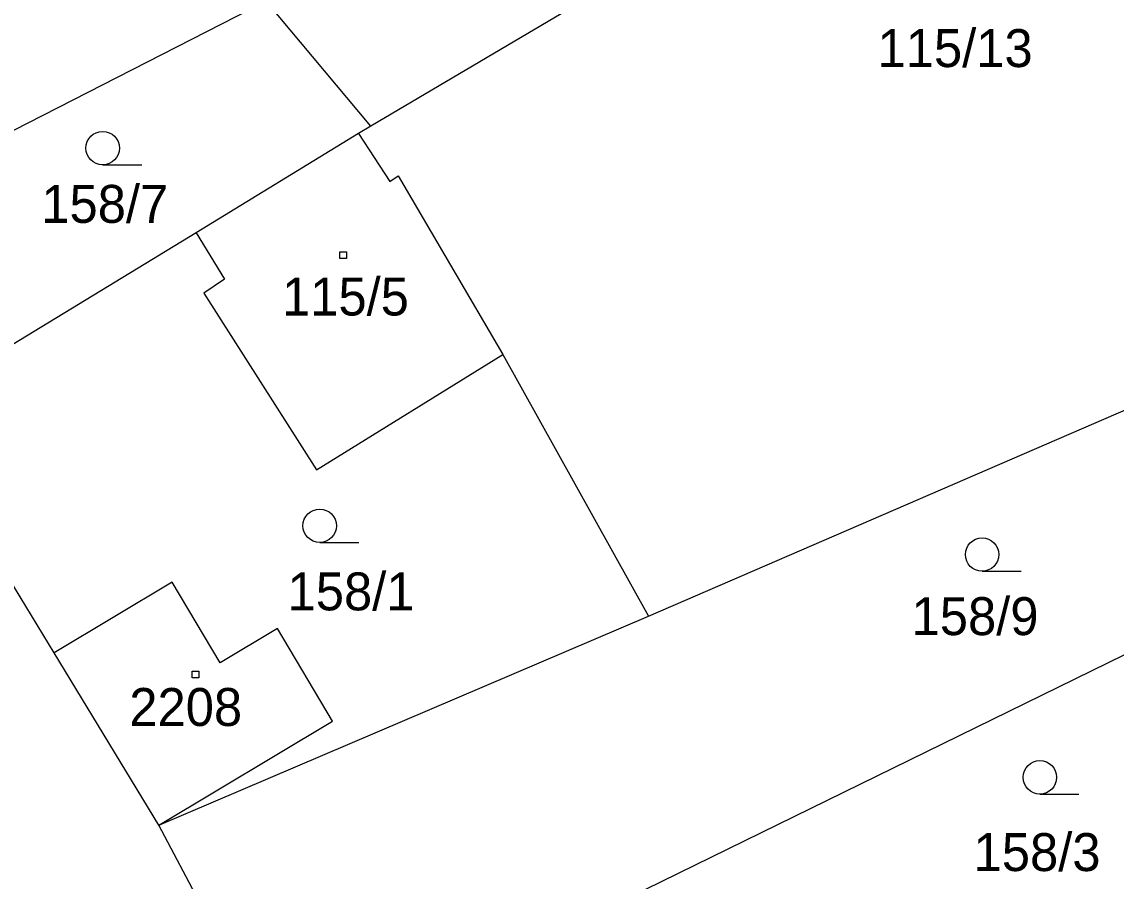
# Model space of a CAD drawing. Extents: x -711879 to -711361, y -1048782 to -1048177.
# Drawn here: x -711718.91 to -711669.86, y -1048658.13 to -1048619.64 of the extents above; entities that cross this region are included whole.
import ezdxf

# ---------------------------------------------------------------- set-up
doc = ezdxf.new("R2010")
doc.units = 0
for name, color, linetype in [('Vrstva 1', 7, 'Continuous'), ('Vrstva 14', 7, 'Continuous'), ('Vrstva 15', 7, 'Continuous'), ('Vrstva 16', 7, 'Continuous'), ('Vrstva 2', 7, 'Continuous'), ('Vrstva 23', 7, 'Continuous'), ('Vrstva 25', 7, 'Continuous'), ('Vrstva 46', 7, 'Continuous')]:
    doc.layers.add(name, color=color, linetype=linetype)

msp = doc.modelspace()

# ---------------------------------------------------------------- linework, layer by layer
at = {"layer": 'Vrstva 1'}
for p, q in [((-711692.51, -1048617.95), (-711703.27, -1048624.31)), ((-711719.96, -1048624.83), (-711707.96, -1048618.7)), ((-711703.27, -1048624.31), (-711707.96, -1048618.7)), ((-711703.27, -1048624.31), (-711703.82, -1048624.64)), ((-711703.82, -1048624.64), (-711711.1, -1048629.08)), ((-711711.1, -1048629.08), (-711724.1, -1048636.99)), ((-711711.1, -1048629.08), (-711709.83, -1048631.16)), ((-711709.83, -1048631.16), (-711710.76, -1048631.79)), ((-711710.76, -1048631.79), (-711705.71, -1048639.71)), ((-711690.83, -1048646.26), (-711663.05, -1048634.25)), ((-711705.71, -1048639.71), (-711697.35, -1048634.53)), ((-711697.35, -1048634.53), (-711690.83, -1048646.26)), ((-711717.47, -1048647.9), (-711724.1, -1048636.99)), ((-711647.12, -1048637.04), (-711707.08, -1048666.39)), ((-711712.17, -1048644.73), (-711717.47, -1048647.9)), ((-711710.02, -1048648.35), (-711712.17, -1048644.73)), ((-711712.77, -1048655.63), (-711690.83, -1048646.26)), ((-711707.45, -1048646.82), (-711710.02, -1048648.35)), ((-711704.99, -1048650.97), (-711707.45, -1048646.82)), ((-711712.77, -1048655.63), (-711717.47, -1048647.9)), ((-711712.77, -1048655.63), (-711704.99, -1048650.97)), ((-711707.08, -1048666.39), (-711712.77, -1048655.63))]:
    msp.add_line(p, q, dxfattribs=at)
at = {"layer": 'Vrstva 2'}
for p, q in [((-711703.82, -1048624.64), (-711702.42, -1048626.78)), ((-711702.42, -1048626.78), (-711702.04, -1048626.53)), ((-711702.04, -1048626.53), (-711697.35, -1048634.53))]:
    msp.add_line(p, q, dxfattribs=at)
at = {"layer": 'Vrstva 23'}
for p, q in [((-711715.29, -1048626.04), (-711713.54, -1048626.04)), ((-711705.56, -1048642.96), (-711703.81, -1048642.96)), ((-711675.87, -1048644.25), (-711674.12, -1048644.25)), ((-711673.28, -1048654.23), (-711671.53, -1048654.23))]:
    msp.add_line(p, q, dxfattribs=at)
for centre in [(-711715.29, -1048625.29), (-711705.56, -1048642.21), (-711675.87, -1048643.5), (-711673.28, -1048653.48)]:
    msp.add_circle(centre, 0.75, dxfattribs=at)
at = {"layer": 'Vrstva 25'}
for p, q in [((-711704.66, -1048629.94), (-711704.36, -1048629.94)), ((-711704.66, -1048630.24), (-711704.66, -1048629.94)), ((-711704.36, -1048630.24), (-711704.66, -1048630.24)), ((-711704.36, -1048629.94), (-711704.36, -1048630.24)), ((-711711.28, -1048648.73), (-711710.98, -1048648.73)), ((-711711.28, -1048649.03), (-711711.28, -1048648.73)), ((-711710.98, -1048648.73), (-711710.98, -1048649.03)), ((-711710.98, -1048649.03), (-711711.28, -1048649.03))]:
    msp.add_line(p, q, dxfattribs=at)
at = {"layer": 'Vrstva 46'}
for p, q in [((-711703.27, -1048624.31), (-711703.27, -1048624.31)), ((-711717.47, -1048647.9), (-711717.47, -1048647.9))]:
    msp.add_line(p, q, dxfattribs=at)

# ---------------------------------------------------------------- texts
at = {"layer": 'Vrstva 14'}
for s, p in [('158/7', (-711718.04, -1048628.64)), ('158/1', (-711707, -1048646)), ('158/9', (-711679.03, -1048647.11)), ('158/3', (-711676.25, -1048657.68))]:
    msp.add_text(s, height=1.7, dxfattribs=at).set_placement(p)
at = {"layer": 'Vrstva 15'}
for s, p in [('115/5', (-711707.25, -1048632.79)), ('2208', (-711714.095, -1048651.18))]:
    msp.add_text(s, height=1.7, dxfattribs=at).set_placement(p)
at = {"layer": 'Vrstva 16'}
msp.add_text('115/13', height=1.7, dxfattribs=at).set_placement((-711680.556, -1048621.66))

doc.saveas('drawing.dxf')
